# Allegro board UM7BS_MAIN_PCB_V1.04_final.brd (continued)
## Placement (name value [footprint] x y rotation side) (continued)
R339  39.2K  [RC0402N]  27.6 26.23 90 bottom
R340  20K  [RC0402N]  26.76 26.23 90 bottom
R341  1K  [RC0402N]  32.66 26.65 180 bottom
R342  10k  [RC0402N]  32.66 27.45 0 bottom
R343  0  [RC0603N]  31.47 32.55 0 bottom
R344  0  [RC0603N]  31.45 31.31 0 bottom
R345  0  [RC0402N]  115.86 93.86 270 bottom
R346  1K  [RC0402N]  31.14 41.12 270 bottom
R347  0  [RC0603N]  34.77 19.95 180 bottom
R348  0  [RC0603N]  26.98 19.88 180 bottom
R349  10k  [RC0402N]  25.37 25.38 180 bottom
R350  10K  [RC0402N]  37.57 37.65 0 bottom
R351  10K  [RC0402N]  39.17 35.26 90 bottom
R352  0  [RC0603N]  21.96 28.35 180 top
R353  100k  [RC0402N]  39.15 31.9 270 bottom
R354  0  [RC0603N]  25.7 29.79 90 top
R355  10k  [RC0402N]  34.98 22.78 180 bottom
R356  1k  [RC0402N]  22.4 29.38 0 top
R357  1k  [RC0402N]  23.86 29.17 270 top
R358  0  [RC0402N]  39.18 37.06 270 bottom
R359  1k  [RC0402N]  40.44 36.21 90 bottom
R360  0  [RC0603N]  9.17 18.35 0 top
R361  0  [RC0603N]  9.16 19.6 0 top
R362  0  [RC0603N]  242.16 10.4 270 top
R363  0  [RC0603N]  240.94 10.4 270 top
R364  10K  [RC0402N]  225.56 19.93 0 bottom
R365  100k  [RC0402N]  223.19 24.58 180 bottom
R366  27K  [RC0402N]  114.86 100.86 90 top
R367  0  [RC0402N]  105.56 94.62 90 bottom
R372  0  [RC0402N]  228.04 16.08 180 bottom
R374  0  [RC0603N]  218.19 15.61 180 bottom
R375  0  [RC0402N]  214.83 13.68 180 bottom
R380  10k  [RC0402N]  217.72 12.25 0 bottom
R385  0  [RC0402N]  64.41 72.7 180 bottom
R386  10k  [RC0402N]  75.38 72.42 0 bottom
R387  0  [RC0402N]  64.41 71.81 180 bottom
R388  0  [RC0603N]  82.34 78.94 0 bottom
R389  0  [RC0805N]  82.34 77 180 bottom
R390  0  [RC0402N]  78.16 70.7 180 bottom
R391  10k  [RC0402N]  77.97 69.53 180 bottom
R392  10k  [RC0402N]  43.84 69.94 0 bottom
R393  0  [RC0402N]  64.41 64.19 180 bottom
R394  10k  [RC0402N]  43.84 70.73 0 bottom
R395  0  [RC0402N]  43.83 65.14 180 bottom
R396  10k  [RC0402N]  54.89 74.6 270 bottom
R397  0  [RC0402N]  43.83 65.97 180 bottom
R398  0  [RC0402N]  46.51 74.6 90 bottom
R399  10k  [RC0402N]  55.9 74.6 270 bottom
R400  0  [RC0402N]  49.94 76.89 90 bottom
R401  10k  [RC0402N]  51.84 74.6 270 bottom
R402  10k  [RC0402N]  52.86 74.6 270 bottom
R403  0  [RC0402N]  49.94 74.6 90 bottom
R404  0  [RC0402N]  45.69 74.6 90 bottom
R405  10k  [RC0402N]  56.92 74.6 270 bottom
R406  100k  [RC0402N]  72.29 70.41 90 bottom
R407  0  [RC0402N]  77.46 62.71 0 top
R408  10k  [RC0402N]  57.94 74.6 270 bottom
R409  0  [RC0603N]  64.79 69.65 0 bottom
R410  0  [RC0603N]  64.79 68.25 0 bottom
R411  0  [RC0402N]  43.84 69.05 180 bottom
R412  0  [RC0402N]  77.46 68.77 180 top
R413  100k  [RC0402N]  72.29 68 270 bottom
R414  10k  [RC0402N]  74.79 68.13 180 bottom
R415  0  [RC0402N]  77.46 67.88 180 top
R416  10k  [RC0402N]  74.79 66.86 180 bottom
R417  0  [RC0402N]  77.46 66.74 180 top
R418  10k  [RC0402N]  43.84 66.85 0 bottom
R419  10k  [RC0402N]  43.84 67.74 0 bottom
R422  0  [RC0402N]  64.41 66.09 180 bottom
R423  0  [RC0402N]  54.86 77 270 bottom
R424  0  [RC0402N]  55.84 77 270 bottom
R427  10k  [RC0402N]  77.97 65.47 180 bottom
R428  100  [RC0402N]  64.4 61.99 0 bottom
R429  0  [RC0402N]  72.29 65.58 90 bottom
R430  0  [RC0402N]  65.85 58.86 90 bottom
R431  0  [RC0402N]  64.41 70.79 180 bottom
R432  0  [RC0402N]  77.46 64.32 180 top
R433  0  [RC0402N]  77.47 63.52 180 top
R434  10k  [RC0402N]  74.79 63.05 180 bottom
R435  0  [RC0402N]  55.14 53.91 90 bottom
R438  0  [RC0402N]  64.41 65.08 180 bottom
R439  0  [RC0402N]  54.37 53.91 270 bottom
R440  0  [RC0402N]  77.45 61.42 180 top
R441  10k  [RC0402N]  76.71 61.56 270 bottom
R442  0  [RC0402N]  58.95 74.6 270 bottom
R443  10k  [RC0402N]  53.6 53.91 90 bottom
R444  0  [RC0402N]  59.97 76.89 90 bottom
R445  100k  [RC0402N]  62.14 63.07 0 top
R446  0  [RC0402N]  59.97 74.6 90 bottom
R447  4.7K  [RC0402N]  67.87 60.9 180 bottom
R448  5.6K  [RC0402N]  67.87 60.11 180 bottom
R449  0  [RC0402N]  49.05 74.6 270 bottom
R450  0  [RC0402N]  50.94 75.02 90 bottom
R452  0  [RC0402N]  48.16 74.6 90 bottom
R453  10k  [RC0402N]  44.25 58.6 90 bottom
R454  0  [RC0402N]  43.73 59.93 0 bottom
R455  0  [RC0402N]  43.84 63.57 0 bottom
R456  10k  [RC0402N]  50.13 60.85 90 top
R457  0  [RC0402N]  44.36 80.19 90 top
R458  0  [RC0402N]  61.75 76 0 bottom
R459  10M  [RC0402N]  63.14 74.85 90 bottom
R460  4.7K  [RC0402N]  47.49 81.68 180 top
R461  4.7K  [RC0402N]  45.48 74.8 90 top
R462  0  [RC0402N]  53.87 74.6 90 bottom
R463  0  [RC0402N]  58.95 76.89 90 bottom
R464  100k  [RC0402N]  51.02 60.85 90 top
R465  0  [RC0603N]  113.36 83.11 180 top
R466  0  [RC0603N]  113.36 85.13 180 top
R467  0  [RC0402N]  44.2 56.3 90 bottom
R469  0  [RC0603N]  9.59 89.65 90 top
R470  0  [RC0603N]  8.38 89.65 90 top
R471  0  [RC0603N]  5.27 89.92 90 top
R472  1.8k  [RC0603N]  18.22 85.73 90 bottom
R473  0  [RC0603N]  6.47 89.92 90 top
R474  1k  [RC0603N]  19.47 85.73 270 bottom
R475  1k  [RC0402N]  16.33 81.88 0 bottom
R476  0  [RC0603N]  11.33 89.4 90 top
R477  0  [RC0603N]  12.54 89.4 90 top
R479  1.8k  [RC0603N]  46.17 91.2 270 bottom
R481  1k  [RC0603N]  48.73 92.7 270 bottom
R482  1k  [RC0402N]  51.51 90.03 90 bottom
R483  0  [RC0603N]  46.96 21.16 0 top
R484  30k  [RC0603N]  42.82 24.8 0 top
R485  0  [RC0603N]  46.96 19.89 0 top
R486  1k  [RC0603N]  42.53 23.47 0 top
R487  1k  [RC0402N]  40.57 22.45 180 top
R488  0  [RC0603N]  62.54 21.2 0 top
R489  0  [RC0603N]  62.54 19.93 0 top
R490  30k  [RC0603N]  59.04 17.44 0 top
R491  1k  [RC0603N]  59.04 18.67 180 top
R492  1k  [RC0402N]  59.74 11.85 180 top
R493  2.2  [RC0805N]  115.73 27.42 0 top
R494  2K  [RC1206N]  140.49 20.92 90 bottom
R495  51m  [RC0805N]  110.5 93.32 0 top
R496  390K  [RC0603N]  140.86 24.77 270 bottom
R497  100  [RC1206N]  137.06 27.56 0 bottom
R498  100k  [RC0402N]  138.04 25.5 0 bottom
R499  1M  [RC0402N]  139.03 21.45 90 bottom
R500  0  [RC0402N]  132.56 21.43 180 bottom
R501  100k  [RC0402N]  130.01 25.4 270 bottom
R509  100  [RC0402N]  100.79 11.32 0 top
R528  0  [RC0402N]  117.57 91.03 180 bottom
R530  0  [RC0402N]  117.57 89.43 0 bottom
R531  1M  [RC0402N]  119.37 89.43 0 bottom
R534  0  [RC0402N]  117.57 90.21 180 bottom
R536  10K  [RC0402N]  104.71 92.17 90 bottom
R537  100k  [RC0402N]  101.77 90.9 180 bottom
R538  1M  [RC0402N]  96.49 90.98 180 bottom
R539  10K  [RC0402N]  146.86 88.35 270 bottom
R540  100k  [RC0402N]  148.69 85.3 0 bottom
R541  0  [RC0402N]  144.47 84.03 90 bottom
R542  0  [RC0402N]  146.86 86.54 270 bottom
R543  0  [RC0402N]  143.68 84.03 90 bottom
R544  1M  [RC0402N]  148.62 80.08 180 bottom
R551  1K  [RC0402N]  36.39 74.55 270 bottom
R552  0  [RC0402N]  50.01 54.11 270 bottom
R553  12k  [RC0402N]  152.63 17.84 90 top
R554  0  [RC0402N]  167.78 37.13 90 bottom
R555  20K  [RC0402N]  141.25 42.01 0 bottom
R556  30k  [RC0603N]  143.49 42.01 0 bottom
R557  100k  [RC0402N]  142.04 45.52 90 bottom
R558  10k  [RC0402N]  154.95 16.47 270 top
R559  0  [RC0402N]  164.99 31.21 180 bottom
R560  0  [RC0402N]  77.07 43.92 0 bottom
R561  0  [RC0402N]  81.53 36.42 180 bottom
R562  0  [RC0402N]  64.41 63.38 0 bottom
R563  0  [RC0402N]  196.11 40.07 90 bottom
R564  0  [RC0402N]  89.58 36.15 0 top
R565  0  [RC0402N]  194.09 48.09 180 bottom
R567  0  [RC0402N]  180.31 74.68 180 bottom
R568  3.3K  [RC0402N]  154.29 42.11 180 top
R569  0  [RC0402N]  180.75 50.57 90 bottom
R570  0  [RC0402N]  188.7 43.1 270 bottom
R571  0  [RC0402N]  187.69 43.09 270 bottom
R572  1k  [RC0402N]  187.69 45.9 270 bottom
R573  1k  [RC0402N]  188.7 45.9 270 bottom
R574  0  [RC0603N]  183.54 28.61 0 top
R575  0  [RC0402N]  185.82 30.03 270 top
R576  10k  [RC0402N]  187.43 35.49 90 bottom
R577  0  [RC0603N]  168.82 87.36 180 top
R578  0  [RC0603N]  168.82 88.63 180 top
R579  2.2  [RC0603N]  180.4 24.37 270 top
R580  2.2  [RC0603N]  155.35 36.42 270 top
R581  2.2  [RC0603N]  198.77 21.88 90 top
R582  0  [RC0603N]  166.76 28.12 270 bottom
R583  0  [RC0603N]  154.81 16.09 0 bottom
R584  10k  [RC0402N]  128.33 11.87 0 top
R585  1k  [RC0402N]  198.37 98.1 180 top
R586  10K_NTC_3300  [RC0402N]  198.37 99.24 180 top
R587  100k  [RC0402N]  164.61 15.28 180 bottom
R588  0  [RC0402N]  195.46 31.87 270 bottom
R589  0  [RC0402N]  162.17 15.8 180 bottom
R590  10k  [RC0402N]  209.07 40.06 0 top
R591  10k  [RC0402N]  67.86 61.78 180 bottom
R592  10k  [RC0402N]  158.6 58.35 270 bottom
R593  182  [RC0402N]  198.75 48.05 270 bottom
R594  0  [RC0402N]  172.11 75.46 0 bottom
R595  0  [RC0402N]  197.68 80.15 90 top
R596  0  [RC0402N]  196.65 80.15 270 top
R597  0  [RC0402N]  183.09 35.49 270 bottom
R598  0  [RC0402N]  182.6 37.65 270 bottom
R599  0  [RC0402N]  174.14 35.48 90 bottom
R600  1k  [RC0402N]  117.05 59.98 270 bottom
R601  1k  [RC0402N]  116.06 59.98 270 bottom
R602  0  [RC0402N]  167.02 51.42 180 bottom
R603  0  [RC0402N]  79.62 57.51 180 bottom
R604  0  [RC0402N]  79.62 58.3 180 bottom
R605  0  [RC0402N]  78.64 56.69 180 bottom
R606  0  [RC0402N]  116.74 84.48 180 bottom
R616  100k  [RC0402N]  116.39 86.85 180 bottom
R636  18.7K  [RC0603N]  119.2 83.11 180 top
R638  12K  [RC0603N]  127.41 83.26 180 bottom
R645  430k  [RC0603N]  114.86 98.1 90 top
R648  430k  [RC0603N]  127.41 82 0 bottom
R663  51m  [RC0805N]  110.5 91.49 0 top
R670  0  [RC0603N]  166.51 28.56 90 top
R681  20K  [RC0402N]  118.8 81.1 180 top
R707  51m  [RC0805N]  110.5 89.71 0 top
R746  10.5K  [RC0402N]  165.71 72.92 90 bottom
R748  1  [RC0603N]  100.36 55.95 90 bottom
R754  16k  [RC0603N]  127.41 84.53 0 bottom
R755  10.9k  [RC0603N]  119.21 86.61 0 top
R756  10k  [RC0603N]  119.21 85.12 180 top
R770  0  [RC0402N]  194.08 45.92 270 bottom
R784  0  [RC0402N]  228.11 14.4 180 bottom
R785  0  [RC0402N]  228.11 13.59 180 bottom
R786  0  [RC0402N]  237.79 14.63 270 bottom
R787  0  [RC0402N]  235.6 14.15 0 bottom
R788  0  [RC0402N]  232.87 16.51 0 bottom
R789  10K  [RC0402N]  232.99 14.72 180 bottom
R790  0  [RC0402N]  232.99 15.53 0 bottom
R800  10k  [RC0402N]  72.32 98.75 90 bottom
R801  1k  [RC0402N]  73.64 99.89 0 bottom
R802  100k  [RC0402N]  73.64 99.07 0 bottom
R821  10  [RC0402N]  167.1 39.45 90 bottom
R823  100  [RC0402N]  195.34 40.07 90 bottom
R825  100  [RC0402N]  155.69 30.29 90 top
R826  0  [RC0402N]  156.36 28.48 90 top
R827  100  [RC0402N]  156.47 30.29 270 top
R828  10k  [RC0402N]  47.32 74.6 90 bottom
R837  0  [RC0402N]  175.63 24.39 0 top
R838  0  [RC0402N]  197.32 20.66 270 bottom
R839  0  [RC0402N]  150.14 28.8 270 top
R840  2.2  [RC0603N]  162.07 10.9 0 top
R841  2.2  [RC0603N]  157.53 11.01 180 top
R842  100k  [RC0402N]  147.36 15.42 270 bottom
R843  0  [RC0402N]  147.66 16.71 0 bottom
R844  0  [RC0402N]  149.55 14.91 0 bottom
R848  0  [RC0402N]  194.85 45.92 270 bottom
R883  39K  [RC0603N]  114.86 100.86 270 top
R958  100k  [RC0402N]  124.42 82.57 0 bottom
R2978  0  [RC0603N]  40.82 89.2 180 top
R2979  0  [RC0603N]  40.82 90.43 180 top
R2980  0  [RC0603N]  35.21 89.91 90 top
R2981  0  [RC0603N]  36.51 89.91 90 top
R2982  0  [RC0603N]  33.53 89.65 90 top
R2983  0  [RC0603N]  32.24 89.65 90 top
R2984  10k  [RC0402N]  182.01 76.93 90 bottom
R3089  0  [RC0402N]  126.81 86.96 0 bottom
R3090  0  [RC0402N]  127.69 86.16 180 bottom
R3091  0  [RC0402N]  116.75 83.6 0 bottom
R3093  100  [RC0402N]  116.39 87.65 180 bottom
R3094  0  [RC0402N]  118.42 82.69 0 bottom
R3095  0  [RC0402N]  105.09 95.94 180 bottom
R3096  1M  [RC0402N]  114.86 98.1 90 top
R3097  0  [RC0402N]  104.62 94.62 90 bottom
R3098  0  [RC0603N]  113.36 81.11 180 top
R3099  0  [RC0603N]  113.36 87.12 180 top
R3100  51m  [RC0805N]  110.5 95.14 0 top
R3101  0  [RC0402N]  103.73 97.39 270 bottom
R3102  0  [RC0402N]  102.88 97.39 270 bottom
R3103  0  [RC0402N]  105.47 97.39 270 bottom
R3104  0  [RC0402N]  104.61 97.39 270 bottom
R3105  100K  [RC0402N]  155.57 50.38 180 bottom
R3106  24k  [RC0402N]  155.57 51.35 0 bottom
R3107  12k  [RC0402N]  155.57 52.18 180 bottom
R3108  100K  [RC0402N]  150.91 50.63 180 bottom
R3109  100K  [RC0402N]  167.86 72.93 270 bottom
R3112  0  [RC0402N]  167.64 69.17 0 bottom
R3113  24K  [RC0402N]  166.51 72.92 270 bottom
SW1  THBM02  [TH-SW-420P-2N]  122.33 8.39 0 top
SW2  SKRMABE010  [SW_330X390P_4N]  59.72 60.17 0 top
TP5  TP  [TEST120]  169.33 55.13 270 top
TP6  TP  [TEST120]  174.64 58.69 90 bottom
TP7  TP  [TEST120]  172.36 60.01 90 bottom
TP10  TP  [TEST120]  185.6 43.03 90 top
TP11  TP  [TEST120]  182.64 54.27 270 bottom
TP12  TP  [TEST120]  81.8 58.79 180 bottom
TP13  TP  [TEST120]  80.8 56.19 180 bottom
TP14  TP  [TEST120]  85.66 60.88 180 bottom
TP15  TP  [TEST120]  81.86 60.43 270 bottom
U1  BSW_MCP_EDS  [BGA78P66X53-1170N]  183.67 62.61 270 top
U2  EN25S64-104RIP  [VSOP127P790-8N]  158.48 44.53 90 top
U3  TPS22965  [SON50P200X200-8N]  152.38 45.16 270 top
U4  KH25U6439FZNI-10G  [SON127P500X600-8AN]  158.48 44.4 90 top
U5  TXS0102DQER  [SON35P100-8N]  114.07 45.47 270 bottom
U6  TXB0104RUTR  [UQFN40P200X170-12N]  77.46 58.23 180 bottom
U7  SN74AHC1G32  [SOT65P210-5N]  180.6 98.02 180 bottom
U8  KLMCG8GE2A  [BGA50P14X28-169AN]  181.97 27.87 270 bottom
U9  GL850G-SSOP28  [SSOP65P780-28N]  175.17 90.4 180 top
U10  TPS51275/C  [QFN40P300X300-20N]  121.2 61.76 90 bottom
U11  TPS650840  [QFN40P800X800-64N]  161.04 22.19 0 top
U15  APL3512A/B  [SOT95P280-5N]  134.94 86.15 0 bottom
U16  PS8625QFN56G  [QFN40P700X700-56AN]  152.51 96.17 180 bottom
U17  AT24C02A  [SOIC127P600-8N]  139.27 100.47 270 top
U18  AT24C02A  [SOIC127P600-8N]  153.66 83.03 180 bottom
U21  APL3512A/B  [SOT95P280-5N]  112.59 29.1 180 bottom
U22  RTL8105E/8111E  [QFN40P600X600-48N]  120.93 38.6 0 bottom
U23  HS00-04078  [SMD-TRANSF-127P-16N]  101.86 35.88 180 top
U24  HS00-04078  [SMD-TRANSF-127P-16N]  101.88 37.15 180 bottom
U25  ALC282  [QFN40P600X600-48AN]  24.83 34.84 180 bottom
U26  5_SN74LVC1G08DCKR  [SOT65P190-5N]  36.69 35.75 180 bottom
U27  SN74LVC1G08DCKR  [SOT65P190-5N]  227.91 18.36 270 bottom
U28  APL3512A/B  [SOT95P280-5N]  218.26 14.31 180 bottom
U29  TXB0101DCKR  [SOT65P210-6N]  78.44 72.46 180 bottom
U30  TXB0104RUTR  [UQFN40P200X170-12N]  77.46 67.63 180 bottom
U31  IT8528E/VG  [LQFP40P1600X1600-128N]  54.13 64.06 180 bottom
U32  TXB0104RUTR  [UQFN40P200X170-12N]  77.46 63.56 180 bottom
U33  SN74LVC1G06DCK  [SOT65P210-5N]  50.39 63.65 90 top
U34  EN25F16-100HIP  [SOIC127P800-8N]  48.92 76.11 90 top
U35  TPS2065  [SOT95P280-5N]  15.85 84.65 270 bottom
U36  TPD2EUSB30DRTR  [SOP35P100-3N]  5.9 91.97 0 top
U37  TPD2EUSB30DRTR  [SOP35P100-3N]  11.97 91.45 0 top
U38  TPS2065  [SOT95P280-5N]  48.96 89.56 0 bottom
U39  TPS2065  [SOT95P280-5N]  41.8 20.36 180 top
U40  TPS2065  [SOT95P280-5N]  60.23 14.68 270 top
U41  APW7228BRI-TRG  [TSSOP65P640-16AN]  121.89 85.88 180 bottom
U42  SN74LVC1G08DCKR  [SOT65P190-5N]  144.64 86.36 180 bottom
U44  APL3512A/B  [SOT95P280-5N]  167.32 34.14 90 bottom
U46  APL5701ABI  [SOT95P280-5N]  144.35 44.76 270 bottom
U53  APL5932C/D  [TDFN50P300X300-10N]  152.71 52.76 180 bottom
U95  GL834L  [QFN50P400X400-24BN]  74.02 94.62 180 bottom
U2523  TPD2EUSB30DRTR  [SOP35P100-3N]  32.82 91.73 0 top
U2524  TPD2EUSB30DRTR  [SOP35P100-3N]  38.71 89.83 90 top
U2525  APL5932C/D  [TDFN50P300X300-10N]  165.04 70.11 270 bottom
X1  OSC-4_7  [OSC170P320X250-4N]  165.6 66.09 180 top
X2  32.768KHz  [OSC120P150X670-4L]  161.71 49.94 180 bottom
X3  Q13MC1461000200SM26BSPRC  [OSC127P200X600-2L]  161.71 49.06 180 bottom
X4  12MHz  [OSC170P320X250-4N]  183.82 89.7 90 top
X5  X3S025000FK1H  [OSC170P320X250-4N]  121.44 29.84 180 bottom
X6  32.768KHz  [OSC120P150X670-4L]  69.37 74.98 270 bottom
X7  Q13MC1461000200SM26BSPRC  [OSC127P200X600-2L]  70.26 74.98 270 bottom

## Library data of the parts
B1 = MIC-2_0
C1 C2 C14-C21 C23 C24 C28 C33-C35 C38-C40 C42-C48 C52 C53 C56-C72 C78 C79 C81-C86 C88-C90 C95-C99 C108-C127 C129-C137 C139 C145-C155 C166 C167 C174 C187 C202 C203 C206 C207 C210 C211 C213 C214 C223-C247 C249-C261 C266 C268 C283 C284 C286 C288 C295 C301 C304-C311 C313-C316 C319 C320 C323-C332 C334 C336 C338-C345 C348-C353 C356 C358 C359 C362 C364-C373 C375-C402 C405 C409 C412-C429 C432 C435-C441 C444-C458 C488 C527 C557 C560-C562 C565 C566 C691 C700-C702 C704-C708 C710 C799-C801 C822 C823 C826-C831 C942 C2833-C2837 = C
C3-C13 C100-C107 C138 C140-C144 C281 C287 C290 C292 C299 C303 C346 C347 C442 C443 C2762 C2763 = C: signal model: C_CC0402N_100NF_100NF
C22 C25-C27 C165 C171 C263 C296 C312 C433 C434 = C: signal model: C_CC0402N_0.01UF_0.01uF
C29-C32 C36 C37 C41 C49-C51 C54 C55 C73-C77 C80 C87 C91-C94 C204 C205 C703 = C: alternate symbols: (T:CC0805N;B:CC0805M)
C128 C158 C160 C161 C164 C168 C173 C183-C186 C188-C190 C193-C195 C197-C201 C212 C215-C222 C264 C265 C267 C300 C333 C355 C357 C360 C361 C363 C374 C410 C411 C459-C462 C464-C466 C468 C607 C727 C992 C2838 = C: alternate symbols: (T:CC0603N;B:CC0603M)
C156 C159 C163 = C: alternate symbols: (T:CC0603N;B:CC0603M); signal model: C_CC0402N_0.01UF_0.01uF
C157 = C: alternate symbols: (T:CC0603N;B:CC0603M); signal model: C_CC0402N_100NF_100NF
C175 C176 C182 = C: alternate symbols: (T:CC0603N;B:CC0603M); signal model: C_CC0402N_0.1U_0.1u
C177-C181 C208 C209 = C: signal model: C_CC0402N_0.1U_0.1u
C297 C335 C337 C354 = C: alternate symbols: (T:CC1206N;B:CC1206M)
C298 C302 C603 = C: alternate symbols: (T:CC1210N;B:CC1210M)
CN1 = CN-DDR3-204
CN3 = CN-SATA-7+15+2-S
CN6 = RJ45_8+2
CN7 CN10 CN12 = CN2+2-S
CN9 = CN75+2-J8
CN11 = CN20+2-S
CN18 J4 = CN-USB-9+4
CN19 CN20 = CN-USB-4+2
CN21 = CN-JACK-3
CN22 = CN2-S
CN23 = SD_11+4
CN24 = BAT_CON_2
CN25 = CN4+2-S
CN26 = CN75+2-S1_1
CN35 = CN40d+2_1
CN40 = CN8d_1
CP1 CP3 CP5 CP8-CP13 CP15-CP21 = C_P: alternate symbols: (T:CCP7343N;B:CCP7343M)
CP4 CP6 CP7 CP14 CP50 = C_P
D1-D3 D12-D14 D17-D21 D26 D27 D30 D38 D42-D44 D2512 D2513 = D
D4 D5 = D_2PN: alternate symbols: (T:SOT95P280-3N;B:SOT95P280-3M)
D8-D11 D22 D23 D28 D29 D31 = D: alternate symbols: (T:sod2514n;B:SOD2514M)
F2-F6 F8 F9 = FUSE
FB1 FB2 FB8-FB14 FB16 FB17 FB19 FB20 FB25 FB27 = FB
FB4-FB7 FB15 FB24 FB37 FB38 = FB: alternate symbols: (T:FB0603N;B:FB0603M)
FIL1-FIL7 FIL9-FIL11 FIL14-FIL16 = FIL4_DXW21BN7511TB
J2 J3 = CN-EARPHONE-5_15
J5 = CN6+2-S
L1-L10 L32 = L
LED1 LED2 = LED
MARK1-MARK8 = MARK
MH1-MH13 = H
Q1 Q16 = NPN-BEC+2R: alternate symbols: (T:SOT65P210-3N;B:SOT65P210-3M)
Q4-Q8 Q31 Q35 Q38 Q40 Q41 Q49 Q51-Q53 = NMOS-GSD
Q9 Q14 Q15 = 7_SM7302ESKP
Q10 Q13 = SI4814: alternate symbols: (T:SOIC127P600-8N;B:SOIC127P600-8M)
Q18 Q21 = PWR_N_MOSFET: alternate symbols: (T:SOIC127P600-8N;B:SOIC127P600-8M)
Q19 Q20 Q22 Q23 Q36 Q42 Q43 Q45 Q46 = NMOS-GSD: alternate symbols: (T:SOT95P240-3N;B:SOT95P240-3M)
Q30 Q37 Q39 Q48 Q50 = NMOS-GSD_0
Q44 = PWR_P_MOSFET: alternate symbols: (T:SOIC127P600-8N;B:SOIC127P600-8M)
Q95 = 3_APM1110NU
R1-R3 R14-R22 R24-R30 R34 R35 R43-R46 R51-R69 R71 R72 R76-R86 R88-R95 R97 R100 R103 R105 R108 R109 R111 R113 R115 R119 R121-R127 R129-R153 R155 R163 R166 R169-R179 R181-R183 R185-R188 R193 R195 R196 R200 R203 R209 R210 R213 R225 R227-R234 R249 R253 R255 R258 R262 R263 R266 R267 R269-R277 R296 R297 R300 R301 R304-R306 R308 R310 R311 R313 R321-R325 R327-R329 R331-R339 R342 R345 R347-R349 R352 R354-R357 R359-R363 R365-R367 R372 R375 R380 R385-R387 R390-R396 R398-R408 R411-R419 R422 R427-R435 R438-R450 R452-R459 R462-R464 R467 R472 R475 R479 R482 R487 R492 R497-R501 R509 R530 R531 R538 R541-R544 R552-R555 R557-R559 R562 R563 R565 R567 R569-R576 R579-R586 R588-R606 R645 R648 R670 R681 R746 R754-R756 R770 R784-R788 R790 R800-R802 R821 R823 R825-R828 R837-R841 R843 R844 R848 R883 R2984 R3089-R3091 R3093-R3095 R3097-R3099 R3101-R3104 R3107 R3112 R3113 = R
R9 R40-R42 R118 R180 R184 R189 R190 R194 R197-R199 R205 R214-R216 R220 R221 R246 R291 R294 R302 R303 R307 R309 R317 R341 R343 R344 R346 R353 R388 R409 R410 R460 R461 R474 R481 R484 R486 R490 R491 R495 R496 R537 R540 R551 R556 R568 R587 R616 R636 R663 R707 R748 R842 R958 R3096 R3100 = R: alternate symbols: (T:RC0603N;B:RC0603M)
R31-R33 R36-R39 R87 R101 R156-R162 R164 R165 R167 R168 R211 R298 = R: signal model: R_RC0402N_0_0
R47-R50 = R: signal model: R_RC0402N_33_33
R70 R73-R75 = R: signal model: R_RC0402N_22_22
R154 R206-R208 = R: signal model: R_0_RC0402N_0_0
R191 R192 R493 = R_0: alternate symbols: (T:RC0603N;B:RC0603M)
R201 R202 R204 = R: alternate symbols: (T:RC0603N;B:RC0603M); signal model: R_0_RC0402N_0_0
R217-R219 R222-R224 R251 R259 R260 R268 R330 R340 R350 R351 R358 R397 R423 R424 R528 R534 R536 R539 R560 R561 R564 R638 R789 R3105 R3106 R3108 R3109 = R_0
R247 R295 R374 R389 = R: alternate symbols: (T:RC0805N;B:RC0805M)
R299 = R: alternate symbols: (T:RC0603N;B:RC0603M); signal model: R_RC0402N_0_0
R312 R314-R316 R318-R320 R326 = R: alternate symbols: (T:RC0603N;B:RC0603M); signal model: C_CC0402N_100NF_100NF
R364 = R_0: signal model: R_RC0402N_0_0
R465 R466 = R: signal model: C_CC0402N_100NF_100NF
R469-R471 R473 R476 R477 R483 R485 R488 R489 R577 R578 R2978-R2983 = R: signal model: R_RC0603N_0_0
R494 = R: alternate symbols: (T:RC1206N;B:RC1206M)
SW1 = SW-2+2
SW2 = SW-4_2
TP5-TP7 TP10-TP15 = TP
U1 = 1170_BSW_MCP_EDS
U2 = 8_EN25S64
U3 = 8+1_TPS22965
U4 = 8+1_KH25U6439F_1
U5 = 8_TXS0102DQER
U6 U30 U32 = 12_TXB0104RUTR
U7 = 5_SN74AHC1G09DCK
U8 = 169_KLMCG8GE2A
U9 = 28_GL850GSSOP28
U10 = 20+1_TPS51275/C
U11 = 64+1_TPS650840
U15 U21 U28 U44 = 5_APL3512
U16 = 56+1_PS8625QFN56G
U17 U18 = 8_AT24C02A
U22 = 48+1_RTL8105E/8111E
U23 U24 = H0056
U25 = 48+1_ALC282
U26 U27 U42 = 5_SN74LVC1G08DCKR
U29 = 6_TXB0101DCKR
U31 = 128_IT8528E/VG
U33 = 5_SN74LVC1G06DCK
U34 = 8_MX25L4005AMC-12G
U35 U38-U40 = 5_APL3511
U36 U37 U2523 U2524 = 3_TPD2EUSB30DRTR
U41 = 16+1_APW7228BRI
U46 = 5_APL5325
U53 U2525 = 10+1_APL5932C/D
U95 = 24+1_GL834L
X1 X4 X5 = OSC-4_7
X2 X6 = OSC-4_4
X3 X7 = OSC-2

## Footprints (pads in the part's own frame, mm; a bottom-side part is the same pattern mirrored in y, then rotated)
BGA50P14X28-169AN
  round 0.254 smd: A4(-1.751,6.752) A6(-0.75,6.752) A9(0.75,6.752) A11(1.75,6.752) AA1(-3.251,-3.251) AA2(-2.751,-3.251) AA3(-2.251,-3.251) AA4(-1.751,-3.251) AA5(-1.25,-3.251) AA6(-0.75,-3.251) AA7(-0.25,-3.251) AA8(0.25,-3.251) AA9(0.75,-3.251) AA10(1.25,-3.251) AA11(1.75,-3.251) AA12(2.25,-3.251) AA13(2.751,-3.251) AA14(3.251,-3.251) AE1(-3.251,-5.251) AE14(3.251,-5.251) AG2(-2.751,-6.251) AG13(2.751,-6.251) AH4(-1.751,-6.752) AH6(-0.75,-6.752) AH9(0.75,-6.752) AH11(1.75,-6.752) B2(-2.751,6.251) B13(2.751,6.251) D1(-3.251,5.251) D14(3.251,5.251) H1(-3.251,3.251) H2(-2.751,3.251) H3(-2.251,3.251) H4(-1.751,3.251) H5(-1.25,3.251) H6(-0.75,3.251) H7(-0.25,3.251) H8(0.25,3.251) H9(0.75,3.251) H10(1.25,3.251) H11(1.75,3.251) H12(2.25,3.251) H13(2.751,3.251) H14(3.251,3.251) J1(-3.251,2.751) J2(-2.751,2.751) J3(-2.251,2.751) J4(-1.751,2.751) J5(-1.25,2.751) J6(-0.75,2.751) J7(-0.25,2.751) J8(0.25,2.751) J9(0.75,2.751) J10(1.25,2.751) J11(1.75,2.751) J12(2.25,2.751) J13(2.751,2.751) J14(3.251,2.751) K1(-3.251,2.251) K2(-2.751,2.251) K3(-2.251,2.251) K4(-1.751,2.251) K5(-1.25,2.251) K6(-0.75,2.251) K7(-0.25,2.251) K8(0.25,2.251) K9(0.75,2.251) K10(1.25,2.251) K11(1.75,2.251) K12(2.25,2.251) K13(2.751,2.251) K14(3.251,2.251) L1(-3.251,1.751) L2(-2.751,1.751) L3(-2.251,1.751) L4(-1.751,1.751) L12(2.25,1.751) L13(2.751,1.751) L14(3.251,1.751) M1(-3.251,1.25) M2(-2.751,1.25) M3(-2.251,1.25) M5(-1.25,1.25) M6(-0.75,1.25) M7(-0.25,1.25) M8(0.25,1.25) M9(0.75,1.25) M10(1.25,1.25) M12(2.25,1.25) M13(2.751,1.25) M14(3.251,1.25) N1(-3.251,0.75) N2(-2.751,0.75) N3(-2.251,0.75) N5(-1.25,0.75) N10(1.25,0.75) N12(2.25,0.75) N13(2.751,0.75) N14(3.251,0.75) P1(-3.251,0.25) P2(-2.751,0.25) P3(-2.251,0.25) P5(-1.25,0.25) P10(1.25,0.25) P12(2.25,0.25) P13(2.751,0.25) P14(3.251,0.25) R1(-3.251,-0.25) R2(-2.751,-0.25) R3(-2.251,-0.25) R5(-1.25,-0.25) R10(1.25,-0.25) R12(2.25,-0.25) R13(2.751,-0.25) R14(3.251,-0.25) T1(-3.251,-0.75) T2(-2.751,-0.75) T3(-2.251,-0.75) T5(-1.25,-0.75) T10(1.25,-0.75) T12(2.25,-0.75) T13(2.751,-0.75) T14(3.251,-0.75) U1(-3.251,-1.25) U2(-2.751,-1.25) U3(-2.251,-1.25) U5(-1.25,-1.25) U6(-0.75,-1.25) U7(-0.25,-1.25) U8(0.25,-1.25) U9(0.75,-1.25) U10(1.25,-1.25) U12(2.25,-1.25) U13(2.751,-1.25) U14(3.251,-1.25) V1(-3.251,-1.75) V2(-2.751,-1.75) V3(-2.251,-1.75) V12(2.25,-1.75) V13(2.751,-1.75) V14(3.251,-1.75) W1(-3.251,-2.25) W2(-2.751,-2.25) W3(-2.251,-2.25) W4(-1.751,-2.25) W5(-1.25,-2.25) W6(-0.75,-2.25) W7(-0.25,-2.25) W8(0.25,-2.25) W9(0.75,-2.25) W10(1.25,-2.25) W11(1.75,-2.25) W12(2.25,-2.25) W13(2.751,-2.25) W14(3.251,-2.25) Y1(-3.251,-2.751) Y2(-2.751,-2.751) Y3(-2.251,-2.751) Y4(-1.751,-2.751) Y5(-1.25,-2.751) Y6(-0.75,-2.751) Y7(-0.25,-2.751) Y8(0.25,-2.751) Y9(0.75,-2.751) Y10(1.25,-2.751) Y11(1.75,-2.751) Y12(2.25,-2.751) Y13(2.751,-2.751) Y14(3.251,-2.751)
BGA78P66X53-1170N
  round 0.47 smd: A3(11.951,-11.814) A52(-12.383,-11.814) B2(12.383,-11.383) B53(-12.814,-11.383) BH1(12.814,11.383) BH53(-12.814,11.383) BJ2(12.383,11.814) BJ52(-12.383,11.814) C1(12.814,-10.951)
  round 0.356 smd: A5(11.17,-11.814) A6(10.447,-11.814) A7(9.748,-11.814) A9(8.836,-11.814) A47(-9.621,-11.814) A48(-10.294,-11.814) A49(-10.992,-11.814) A51(-11.773,-11.814) B4(11.632,-11.238) B5(11.038,-11.222) B6(10.445,-11.221) B8(9.258,-11.224) B46(-9.258,-11.224) B48(-10.445,-11.221) B49(-11.038,-11.222) B50(-11.632,-11.238) B52(-12.225,-11.225) BC1(12.814,8.621) BC2(12.246,8.852) BC52(-12.246,8.852) BC53(-12.814,8.621) BD1(12.814,9.294) BD2(12.221,9.445) BD52(-12.221,9.445) BD53(-12.814,9.294) BE1(12.814,9.992) BE2(12.222,10.038) BE52(-12.222,10.038) BE53(-12.814,9.992) BF2(12.238,10.632) BF52(-12.238,10.632) BG1(12.814,10.773) BG3(11.644,10.644) BG51(-11.644,10.644) BG53(-12.814,10.773) BH2(12.225,11.225) BH4(11.632,11.238) BH5(11.038,11.222) BH6(10.445,11.221) BH8(9.258,11.224) BH46(-9.258,11.224) BH48(-10.445,11.221) BH49(-11.038,11.222) BH50(-11.632,11.238) BH52(-12.225,11.225) BJ3(11.773,11.814) BJ5(10.992,11.814) BJ6(10.294,11.814) BJ7(9.621,11.814) BJ47(-9.621,11.814) BJ48(-10.294,11.814) BJ49(-10.992,11.814) BJ51(-11.773,11.814) C3(11.644,-10.644) C51(-11.644,-10.644) C53(-12.814,-10.773) D2(12.238,-10.632) D52(-12.238,-10.632) E1(12.814,-10.17) E2(12.222,-10.038) E52(-12.222,-10.038) E53(-12.814,-9.992) F1(12.814,-9.447) F2(12.221,-9.445) F52(-12.221,-9.445) F53(-12.814,-9.294) G1(12.814,-8.679) G2(12.246,-8.852) G52(-12.246,-8.852) G53(-12.814,-8.621) J1(12.814,-7.816)
  oval 0.254x0.343 smd: A11(7.774,-11.814) A13(6.803,-11.814) A15(5.831,-11.814) A17(4.859,-11.814) A19(3.887,-11.814) A21(2.915,-11.814) A23(1.944,-11.814) A25(0.972,-11.814) A27(0,-11.814) A29(-0.972,-11.814) A31(-1.944,-11.814) A33(-2.915,-11.814) A35(-3.887,-11.814) A37(-4.859,-11.814) A39(-5.831,-11.814) A41(-6.803,-11.814) A43(-7.774,-11.814) A45(-8.746,-11.814) BJ9(8.746,11.814) BJ11(7.774,11.814) BJ13(6.803,11.814) BJ15(5.831,11.814) BJ17(4.859,11.814) BJ19(3.887,11.814) BJ21(2.915,11.814) BJ23(1.944,11.814) BJ25(0.972,11.814) BJ27(0,11.814) BJ29(-0.972,11.814) BJ31(-1.944,11.814) BJ33(-2.915,11.814) BJ35(-3.887,11.814) BJ37(-4.859,11.814) BJ39(-5.831,11.814) BJ41(-6.803,11.814) BJ43(-7.774,11.814) BJ45(-8.746,11.814)
  oval 0.343x0.254 smd: AA1(12.814,-1.944) AA53(-12.814,-1.944) AC1(12.814,-0.972) AC53(-12.814,-0.972) AE1(12.814,0) AE53(-12.814,0) AG1(12.814,0.972) AG53(-12.814,0.972) AJ1(12.814,1.944) AJ53(-12.814,1.944) AL1(12.814,2.915) AL53(-12.814,2.915) AN1(12.814,3.887) AN53(-12.814,3.887) AR1(12.814,4.859) AR53(-12.814,4.859) AU1(12.814,5.831) AU53(-12.814,5.831) AW1(12.814,6.803) AW53(-12.814,6.803) BA1(12.814,7.774) BA53(-12.814,7.774) J53(-12.814,-7.774) L1(12.814,-6.803) L53(-12.814,-6.803) N1(12.814,-5.831) N53(-12.814,-5.831) R1(12.814,-4.859) R53(-12.814,-4.859) U1(12.814,-3.887) U53(-12.814,-3.887) W1(12.814,-2.915) W53(-12.814,-2.915)
  round 0.279 smd: AA3(12.071,-1.944) AA51(-12.071,-1.944) AB2(12.429,-1.458) AB3(11.73,-1.458) AB51(-11.73,-1.458) AB52(-12.429,-1.458) AC3(12.071,-0.972) AC51(-12.071,-0.972) AD2(12.429,-0.486) AD3(11.715,-0.48) AD51(-11.715,-0.48) AD52(-12.429,-0.486) AE3(12.071,0) AE4(11.366,0) AE50(-11.366,0) AE51(-12.071,0) AF2(12.429,0.486) AF3(11.715,0.48) AF51(-11.715,0.48) AF52(-12.429,0.486) AG3(12.071,0.972) AG51(-12.071,0.972) AH2(12.429,1.458) AH3(11.73,1.458) AH51(-11.73,1.458) AH52(-12.429,1.458) AJ3(12.071,1.944) AJ51(-12.071,1.944) AK2(12.429,2.43) AK3(11.73,2.43) AK51(-11.73,2.43) AK52(-12.429,2.43) AL3(12.071,2.915) AL51(-12.071,2.915) AM2(12.429,3.401) AM3(11.73,3.401) AM51(-11.73,3.401) AM52(-12.429,3.401) AN3(12.071,3.887) AN51(-12.071,3.887) AP2(12.429,4.373) AP3(11.73,4.373) AP51(-11.73,4.373) AP52(-12.429,4.373) AR3(12.071,4.859) AR51(-12.071,4.859) AT2(12.429,5.345) AT3(11.73,5.345) AT51(-11.73,5.345) AT52(-12.429,5.345) AU3(12.071,5.831) AU51(-12.071,5.831) AV2(12.429,6.317) AV3(11.73,6.317) AV51(-11.73,6.317) AV52(-12.429,6.317) AW3(12.071,6.803) AW51(-12.071,6.803) AY2(12.429,7.289) AY3(11.73,7.289) AY51(-11.73,7.289) AY52(-12.429,7.289) B10(8.26,-11.429) B12(7.289,-11.429) B14(6.317,-11.429) B16(5.345,-11.429) B18(4.373,-11.429) B20(3.401,-11.429) B22(2.43,-11.429) B24(1.458,-11.429) B26(0.486,-11.429) B28(-0.486,-11.429) B30(-1.458,-11.429) B32(-2.43,-11.429) B34(-3.401,-11.429) B36(-4.373,-11.429) B38(-5.345,-11.429) B40(-6.317,-11.429) B42(-7.289,-11.429) B44(-8.26,-11.429) BA3(12.071,7.774) BA51(-12.071,7.774) BB3(11.929,8.351) BB51(-11.929,8.351) BF27(0,10.366) BG9(8.698,11.028) BG11(7.774,11.071) BG12(7.289,10.73) BG13(6.803,11.071) BG14(6.317,10.73) BG15(5.831,11.071) BG16(5.345,10.73) BG17(4.859,11.071) BG18(4.373,10.73) BG19(3.887,11.071) BG20(3.401,10.73) BG21(2.915,11.071) BG22(2.43,10.73) BG23(1.944,11.071) BG24(1.458,10.73) BG25(0.972,11.071) BG26(0.48,10.715) BG27(0,11.071) BG28(-0.48,10.715) BG29(-0.972,11.071) BG30(-1.458,10.73) BG31(-1.944,11.071) BG32(-2.43,10.73) BG33(-2.915,11.071) BG34(-3.401,10.73) BG35(-3.887,11.071) BG36(-4.373,10.73) BG37(-4.859,11.071) BG38(-5.345,10.73) BG39(-5.831,11.071) BG40(-6.317,10.73) BG41(-6.803,11.071) BG42(-7.289,10.73) BG43(-7.774,11.071) BG45(-8.698,11.028) BH10(8.26,11.429) BH12(7.289,11.429) BH14(6.317,11.429) BH16(5.345,11.429) BH18(4.373,11.429) BH20(3.401,11.429) BH22(2.43,11.429) BH24(1.458,11.429) BH26(0.486,11.429) BH28(-0.486,11.429) BH30(-1.458,11.429) BH32(-2.43,11.429) BH34(-3.401,11.429) BH36(-4.373,11.429) BH38(-5.345,11.429) BH40(-6.317,11.429) BH42(-7.289,11.429) BH44(-8.26,11.429) C9(8.698,-11.028) C11(7.774,-11.071) C12(7.289,-10.73) C13(6.803,-11.071) C14(6.317,-10.73) C15(5.831,-11.071) C16(5.345,-10.73) C17(4.859,-11.071) C18(4.373,-10.73) C19(3.887,-11.071) C20(3.401,-10.73) C21(2.915,-11.071) C22(2.43,-10.73) C23(1.944,-11.071) C24(1.458,-10.73) C25(0.972,-11.071) C26(0.48,-10.715) C27(0,-11.071) C28(-0.48,-10.715) C29(-0.972,-11.071) C30(-1.458,-10.73) C31(-1.944,-11.071) C32(-2.43,-10.73) C33(-2.915,-11.071) C34(-3.401,-10.73) C35(-3.887,-11.071) C36(-4.373,-10.73) C37(-4.859,-11.071) C38(-5.345,-10.73) C39(-5.831,-11.071) C40(-6.317,-10.73) C41(-6.803,-11.071) C42(-7.289,-10.73) C43(-7.774,-11.071) C45(-8.698,-11.028) D27(0,-10.366) H3(11.929,-8.351) H51(-11.929,-8.351) J3(12.071,-7.774) J51(-12.071,-7.774) K2(12.429,-7.289) K3(11.73,-7.289) K51(-11.73,-7.289) K52(-12.429,-7.289) L3(12.071,-6.803) L51(-12.071,-6.803) M2(12.429,-6.317) M3(11.73,-6.317) M51(-11.73,-6.317) M52(-12.429,-6.317) N3(12.071,-5.831) N51(-12.071,-5.831) P2(12.429,-5.345) P3(11.73,-5.345) P51(-11.73,-5.345) P52(-12.429,-5.345) R3(12.071,-4.859) R51(-12.071,-4.859) T2(12.429,-4.373) T3(11.73,-4.373) T51(-11.73,-4.373) T52(-12.429,-4.373) U3(12.071,-3.887) U51(-12.071,-3.887) V2(12.429,-3.401) V3(11.73,-3.401) V51(-11.73,-3.401) V52(-12.429,-3.401) W3(12.071,-2.915) W51(-12.071,-2.915) Y2(12.429,-2.43) Y3(11.73,-2.43) Y51(-11.73,-2.43) Y52(-12.429,-2.43)
  round 0.33 smd: AA16(5.307,-1.961) AA18(4.549,-1.961) AA19(3.791,-1.961) AA21(3.033,-1.961) AA22(2.275,-1.961) AA24(1.516,-1.961) AA25(0.758,-1.961) AA27(0,-1.961) AA29(-0.758,-1.961) AA30(-1.516,-1.961) AA32(-2.275,-1.961) AA33(-3.033,-1.961) AA35(-3.791,-1.961) AA36(-4.549,-1.961) AA38(-5.307,-1.961) AC16(5.307,-1.177) AC18(4.549,-1.177) AC19(3.791,-1.177) AC21(3.033,-1.177) AC22(2.275,-1.177) AC24(1.516,-1.177) AC25(0.758,-1.177) AC27(0,-1.177) AC29(-0.758,-1.177) AC30(-1.516,-1.177) AC32(-2.275,-1.177) AC33(-3.033,-1.177) AC35(-3.791,-1.177) AC36(-4.549,-1.177) AC38(-5.307,-1.177) AD16(5.307,-0.392) AD18(4.549,-0.392) AD19(3.791,-0.392) AD21(3.033,-0.392) AD22(2.275,-0.392) AD24(1.516,-0.392) AD25(0.758,-0.392) AD27(0,-0.392) AD29(-0.758,-0.392) AD30(-1.516,-0.392) AD32(-2.275,-0.392) AD33(-3.033,-0.392) AD35(-3.791,-0.392) AD36(-4.549,-0.392) AD38(-5.307,-0.392) AF16(5.307,0.392) AF18(4.549,0.392) AF19(3.791,0.392) AF21(3.033,0.392) AF22(2.275,0.392) AF24(1.516,0.392) AF25(0.758,0.392) AF27(0,0.392) AF29(-0.758,0.392) AF30(-1.516,0.392) AF32(-2.275,0.392) AF33(-3.033,0.392) AF35(-3.791,0.392) AF36(-4.549,0.392) AF38(-5.307,0.392) AG16(5.307,1.177) AG18(4.549,1.177) AG19(3.791,1.177) AG21(3.033,1.177) AG22(2.275,1.177) AG24(1.516,1.177) AG25(0.758,1.177) AG27(0,1.177) AG29(-0.758,1.177) AG30(-1.516,1.177) AG32(-2.275,1.177) AG33(-3.033,1.177) AG35(-3.791,1.177) AG36(-4.549,1.177) AG38(-5.307,1.177) AJ16(5.307,1.961) AJ18(4.549,1.961) AJ19(3.791,1.961) AJ21(3.033,1.961) AJ22(2.275,1.961) AJ24(1.516,1.961) AJ25(0.758,1.961) AJ27(0,1.961) AJ29(-0.758,1.961) AJ30(-1.516,1.961) AJ32(-2.275,1.961) AJ33(-3.033,1.961) AJ35(-3.791,1.961) AJ36(-4.549,1.961) AJ38(-5.307,1.961) AK16(5.307,2.745) AK18(4.549,2.745) AK19(3.791,2.745) AK21(3.033,2.745) AK22(2.275,2.745) AK24(1.516,2.745) AK25(0.758,2.745) AK27(0,2.745) AK29(-0.758,2.745) AK30(-1.516,2.745) AK32(-2.275,2.745) AK33(-3.033,2.745) AK35(-3.791,2.745) AK36(-4.549,2.745) AK38(-5.307,2.745) AM16(5.307,3.53) AM18(4.549,3.53) AM19(3.791,3.53) AM21(3.033,3.53) AM22(2.275,3.53) AM24(1.516,3.53) AM25(0.758,3.53) AM27(0,3.53) AM29(-0.758,3.53) AM30(-1.516,3.53) AM32(-2.275,3.53) AM33(-3.033,3.53) AM35(-3.791,3.53) AM36(-4.549,3.53) AM38(-5.307,3.53) AN16(5.307,4.314) AN18(4.549,4.314) AN19(3.791,4.314) AN21(3.033,4.314) AN22(2.275,4.314) AN24(1.516,4.314) AN25(0.758,4.314) AN27(0,4.314) AN29(-0.758,4.314) AN30(-1.516,4.314) AN32(-2.275,4.314) AN33(-3.033,4.314) AN35(-3.791,4.314) AN36(-4.549,4.314) AN38(-5.307,4.314) U16(5.307,-4.314) U18(4.549,-4.314) U19(3.791,-4.314) U21(3.033,-4.314) U22(2.275,-4.314) U24(1.516,-4.314) U25(0.758,-4.314) U27(0,-4.314) U29(-0.758,-4.314) U30(-1.516,-4.314) U32(-2.275,-4.314) U33(-3.033,-4.314) U35(-3.791,-4.314) U36(-4.549,-4.314) U38(-5.307,-4.314) V16(5.307,-3.53) V18(4.549,-3.53) V19(3.791,-3.53) V21(3.033,-3.53) V22(2.275,-3.53) V24(1.516,-3.53) V25(0.758,-3.53) V27(0,-3.53) V29(-0.758,-3.53) V30(-1.516,-3.53) V32(-2.275,-3.53) V33(-3.033,-3.53) V35(-3.791,-3.53) V36(-4.549,-3.53) V38(-5.307,-3.53) Y16(5.307,-2.745) Y18(4.549,-2.745) Y19(3.791,-2.745) Y21(3.033,-2.745) Y22(2.275,-2.745) Y24(1.516,-2.745) Y25(0.758,-2.745) Y27(0,-2.745) Y29(-0.758,-2.745) Y30(-1.516,-2.745) Y32(-2.275,-2.745) Y33(-3.033,-2.745) Y35(-3.791,-2.745) Y36(-4.549,-2.745) Y38(-5.307,-2.745)
  round 0.305 smd: AB4(11.137,-1.448) AB6(10.463,-1.448) AB7(9.752,-1.448) AB9(9.041,-1.448) AB10(8.33,-1.448) AB12(7.618,-1.448) AB13(6.907,-1.448) AB14(6.196,-1.448) AB40(-6.196,-1.448) AB41(-6.907,-1.448) AB42(-7.618,-1.448) AB44(-8.33,-1.448) AB45(-9.041,-1.448) AB47(-9.752,-1.448) AB48(-10.463,-1.448) AB50(-11.137,-1.448) AD4(10.995,-0.463) AD6(10.404,-0.525) AD7(9.752,-0.475) AD9(9.041,-0.475) AD10(8.33,-0.475) AD12(7.618,-0.475) AD13(6.907,-0.475) AD14(6.196,-0.475) AD40(-6.196,-0.475) AD41(-6.907,-0.475) AD42(-7.618,-0.475) AD44(-8.33,-0.475) AD45(-9.041,-0.475) AD47(-9.752,-0.475) AD48(-10.404,-0.525) AD50(-10.995,-0.463) AE6(10.108,0) AE8(9.396,0) AE9(8.685,0) AE11(7.974,0) AE12(7.263,0) AE14(6.552,0) AE40(-6.552,0) AE42(-7.263,0) AE43(-7.974,0) AE45(-8.685,0) AE46(-9.396,0) AE48(-10.108,0) AF4(10.995,0.463) AF6(10.404,0.525) AF7(9.752,0.475) AF9(9.041,0.475) AF10(8.33,0.475) AF12(7.618,0.475) AF13(6.907,0.475) AF14(6.196,0.475) AF40(-6.196,0.475) AF41(-6.907,0.475) AF42(-7.618,0.475) AF44(-8.33,0.475) AF45(-9.041,0.475) AF47(-9.752,0.475) AF48(-10.404,0.525) AF50(-10.995,0.463) AH4(11.137,1.448) AH6(10.463,1.448) AH7(9.752,1.448) AH9(9.041,1.448) AH10(8.33,1.448) AH12(7.618,1.448) AH13(6.907,1.448) AH14(6.196,1.448) AH40(-6.196,1.448) AH41(-6.907,1.448) AH42(-7.618,1.448) AH44(-8.33,1.448) AH45(-9.041,1.448) AH47(-9.752,1.448) AH48(-10.463,1.448) AH50(-11.137,1.448) AK4(11.137,2.439) AK6(10.463,2.439) AK7(9.752,2.439) AK9(9.041,2.439) AK10(8.33,2.439) AK12(7.618,2.439) AK13(6.907,2.439) AK14(6.196,2.439) AK40(-6.196,2.439) AK41(-6.907,2.439) AK42(-7.618,2.439) AK44(-8.33,2.439) AK45(-9.041,2.439) AK47(-9.752,2.439) AK48(-10.463,2.439) AK50(-11.137,2.439) AM4(11.137,3.386) AM6(10.463,3.412) AM7(9.752,3.412) AM9(9.041,3.412) AM10(8.33,3.412) AM12(7.618,3.412) AM13(6.907,3.412) AM14(6.196,3.412) AM40(-6.196,3.412) AM41(-6.907,3.412) AM42(-7.618,3.412) AM44(-8.33,3.412) AM45(-9.041,3.412) AM47(-9.752,3.412) AM48(-10.463,3.412) AM50(-11.137,3.386) AN5(10.819,3.887) AN6(10.108,3.887) AN8(9.396,3.887) AN9(8.685,3.887) AN11(7.974,3.887) AN12(7.263,3.887) AN14(6.552,3.887) AN40(-6.552,3.887) AN42(-7.263,3.887) AN43(-7.974,3.887) AN45(-8.685,3.887) AN46(-9.396,3.887) AN48(-10.108,3.887) AN49(-10.819,3.887) AP4(11.137,4.388) AP6(10.463,4.362) AP7(9.752,4.362) AP9(9.041,4.362) AP10(8.33,4.362) AP12(7.618,4.362) AP13(6.907,4.362) AP14(6.196,4.362) AP40(-6.196,4.362) AP41(-6.907,4.362) AP42(-7.618,4.362) AP44(-8.33,4.362) AP45(-9.041,4.362) AP47(-9.752,4.362) AP48(-10.463,4.362) AP50(-11.137,4.388) AT4(11.137,5.336) AT6(10.463,5.336) AT7(9.752,5.336) AT9(9.041,5.336) AT10(8.33,5.336) AT12(7.618,5.336) AT13(6.907,5.336) AT14(6.305,5.336) AT16(5.336,5.196) AT18(4.362,5.196) AT19(3.887,5.552) AT20(3.412,5.196) AT22(2.439,5.196) AT24(1.448,5.196) AT26(0.475,5.196) AT27(0,5.552) AT28(-0.475,5.196) AT30(-1.448,5.196) AT32(-2.439,5.196) AT34(-3.412,5.196) AT35(-3.887,5.552) AT36(-4.362,5.196) AT38(-5.336,5.196) AT40(-6.305,5.336) AT41(-6.907,5.336) AT42(-7.618,5.336) AT44(-8.33,5.336) AT45(-9.041,5.336) AT47(-9.752,5.336) AT48(-10.463,5.336) AT50(-11.137,5.336) AU16(5.336,5.907) AU18(4.362,5.907) AU20(3.412,5.907) AU22(2.439,5.907) AU24(1.448,5.907) AU26(0.475,5.907) AU28(-0.475,5.907) AU30(-1.448,5.907) AU32(-2.439,5.907) AU34(-3.412,5.907) AU36(-4.362,5.907) AU38(-5.336,5.907) AV4(11.137,6.326) AV6(10.463,6.326) AV7(9.752,6.326) AV9(9.041,6.326) AV10(8.33,6.326) AV12(7.618,6.326) AV13(6.907,6.326) AV14(6.326,6.446) AV16(5.336,6.618) AV18(4.362,6.618) AV19(3.887,6.263) AV20(3.412,6.618) AV22(2.439,6.618) AV24(1.448,6.618) AV26(0.475,6.618) AV27(0,6.263) AV28(-0.475,6.618) AV30(-1.448,6.618) AV32(-2.439,6.618) AV34(-3.412,6.618) AV35(-3.887,6.263) AV36(-4.362,6.618) AV38(-5.336,6.618) AV40(-6.326,6.446) AV41(-6.907,6.326) AV42(-7.618,6.326) AV44(-8.33,6.326) AV45(-9.041,6.326) AV47(-9.752,6.326) AV48(-10.463,6.326) AV50(-11.137,6.326) AW13(6.751,6.915) AW19(3.887,6.974) AW27(0,6.974) AW35(-3.887,6.974) AW41(-6.751,6.915) AY4(11.137,7.317) AY6(10.463,7.317) AY7(9.752,7.317) AY9(9.041,7.317) AY10(8.33,7.317) AY12(7.317,7.34) AY14(6.326,7.33) AY16(5.336,7.33) AY18(4.362,7.33) AY20(3.412,7.33) AY22(2.439,7.33) AY24(1.448,7.33) AY26(0.475,7.33) AY28(-0.475,7.33) AY30(-1.448,7.33) AY32(-2.439,7.33) AY34(-3.412,7.33) AY36(-4.362,7.33) AY38(-5.336,7.33) AY40(-6.326,7.33) AY42(-7.317,7.34) AY44(-8.33,7.317) AY45(-9.041,7.317) AY47(-9.752,7.317) AY48(-10.463,7.317) AY50(-11.137,7.317) B7(9.852,-11.23) B47(-9.852,-11.23) BA12(7.317,8.041) BA14(6.326,8.041) BA16(5.336,8.041) BA18(4.362,8.041) BA19(3.887,7.685) BA20(3.412,8.041) BA22(2.439,8.041) BA24(1.448,8.041) BA26(0.475,8.041) BA27(0,7.685) BA28(-0.475,8.041) BA30(-1.448,8.041) BA32(-2.439,8.041) BA34(-3.412,8.041) BA35(-3.887,7.685) BA36(-4.362,8.041) BA38(-5.336,8.041) BA40(-6.326,8.041) BA42(-7.317,8.041) BB4(11.258,8.307) BB5(10.547,8.307) BB7(9.835,8.307) BB8(9.124,8.307) BB10(8.307,8.17) BB19(3.887,8.396) BB27(0,8.396) BB35(-3.887,8.396) BB44(-8.307,8.17) BB46(-9.124,8.307) BB47(-9.835,8.307) BB49(-10.547,8.307) BB50(-11.258,8.307) BC10(8.307,8.764) BC12(7.317,8.752) BC14(6.326,8.752) BC16(5.336,8.752) BC18(4.362,8.752) BC20(3.412,8.752) BC22(2.439,8.752) BC24(1.448,8.752) BC26(0.475,8.752) BC28(-0.475,8.752) BC30(-1.448,8.752) BC32(-2.439,8.752) BC34(-3.412,8.752) BC36(-4.362,8.752) BC38(-5.336,8.752) BC40(-6.326,8.752) BC42(-7.317,8.752) BC44(-8.307,8.764) BD5(10.565,9.302) BD7(9.712,9.302) BD10(8.307,9.457) BD12(7.317,9.463) BD14(6.326,9.463) BD16(5.336,9.463) BD18(4.362,9.463) BD19(3.887,9.108) BD20(3.412,9.463) BD22(2.439,9.463) BD24(1.448,9.463) BD26(0.525,9.404) BD27(0,9.108) BD28(-0.525,9.404) BD30(-1.448,9.463) BD32(-2.439,9.463) BD34(-3.412,9.463) BD35(-3.887,9.108) BD36(-4.362,9.463) BD38(-5.336,9.463) BD40(-6.326,9.463) BD42(-7.317,9.463) BD44(-8.307,9.457) BD47(-9.712,9.302) BD49(-10.565,9.302) BE3(11.643,9.58) BE8(9.32,9.747) BE19(3.887,9.819) BE35(-3.887,9.819) BE46(-9.32,9.747) BE51(-11.643,9.58) BF4(11.163,10.163) BF6(10.113,10.238) BF10(8.307,10.168) BF12(7.317,10.137) BF14(6.326,10.137) BF16(5.336,10.137) BF18(4.388,10.137) BF20(3.386,10.137) BF22(2.439,10.137) BF24(1.448,10.137) BF26(0.463,9.995) BF28(-0.463,9.995) BF30(-1.448,10.137) BF32(-2.439,10.137) BF34(-3.386,10.137) BF36(-4.388,10.137) BF38(-5.336,10.137) BF40(-6.326,10.137) BF42(-7.317,10.137) BF44(-8.307,10.168) BF48(-10.113,10.238) BF50(-11.163,10.163) BG5(10.58,10.643) BG7(9.553,10.709) BG47(-9.553,10.709) BG49(-10.58,10.643) BH7(9.852,11.23) BH47(-9.852,11.23) C5(10.58,-10.643) C7(9.553,-10.709) C47(-9.553,-10.709) C49(-10.58,-10.643) D4(11.163,-10.163) D6(10.113,-10.238) D10(8.307,-10.168) D12(7.317,-10.137) D14(6.326,-10.137) D16(5.336,-10.137) D18(4.388,-10.137) D20(3.386,-10.137) D22(2.439,-10.137) D24(1.448,-10.137) D26(0.463,-9.995) D28(-0.463,-9.995) D30(-1.448,-10.137) D32(-2.439,-10.137) D34(-3.386,-10.137) D36(-4.388,-10.137) D38(-5.336,-10.137) D40(-6.326,-10.137) D42(-7.317,-10.137) D44(-8.307,-10.168) D48(-10.113,-10.238) D50(-11.163,-10.163) E3(11.643,-9.58) E8(9.32,-9.747) E19(3.887,-9.819) E35(-3.887,-9.819) E46(-9.32,-9.747) E51(-11.643,-9.58) F5(10.565,-9.302) F7(9.712,-9.302) F10(8.307,-9.457) F12(7.317,-9.463) F14(6.326,-9.463) F16(5.336,-9.463) F18(4.362,-9.463) F19(3.887,-9.108) F20(3.412,-9.463) F22(2.439,-9.463) F24(1.448,-9.463) F26(0.525,-9.404) F27(0,-9.108) F28(-0.525,-9.404) F30(-1.448,-9.463) F32(-2.439,-9.463) F34(-3.412,-9.463) F35(-3.887,-9.108) F36(-4.362,-9.463) F38(-5.336,-9.463) F40(-6.326,-9.463) F42(-7.317,-9.463) F44(-8.307,-9.457) F47(-9.712,-9.302) F49(-10.565,-9.302) G10(8.307,-8.764) G12(7.317,-8.752) G14(6.326,-8.752) G16(5.336,-8.752) G18(4.362,-8.752) G20(3.412,-8.752) G22(2.439,-8.752) G24(1.448,-8.752) G26(0.475,-8.752) G28(-0.475,-8.752) G30(-1.448,-8.752) G32(-2.439,-8.752) G34(-3.412,-8.752) G36(-4.362,-8.752) G38(-5.336,-8.752) G40(-6.326,-8.752) G42(-7.317,-8.752) G44(-8.307,-8.764) H4(11.258,-8.307) H5(10.547,-8.307) H7(9.835,-8.307) H8(9.124,-8.307) H10(8.307,-8.17) H19(3.887,-8.396) H27(0,-8.396) H35(-3.887,-8.396) H44(-8.307,-8.17) H46(-9.124,-8.307) H47(-9.835,-8.307) H49(-10.547,-8.307) H50(-11.258,-8.307) J12(7.317,-8.041) J14(6.326,-8.041) J16(5.336,-8.041) J18(4.362,-8.041) J19(3.887,-7.685) J20(3.412,-8.041) J22(2.439,-8.041) J24(1.448,-8.041) J26(0.475,-8.041) J27(0,-7.685) J28(-0.475,-8.041) J30(-1.448,-8.041) J32(-2.439,-8.041) J34(-3.412,-8.041) J35(-3.887,-7.685) J36(-4.362,-8.041) J38(-5.336,-8.041) J40(-6.326,-8.041) J42(-7.317,-8.041) K4(11.137,-7.317) K6(10.463,-7.317) K7(9.752,-7.317) K9(9.041,-7.317) K10(8.33,-7.317) K12(7.317,-7.34) K14(6.326,-7.33) K16(5.336,-7.33) K18(4.362,-7.33) K20(3.412,-7.33) K22(2.439,-7.33) K24(1.448,-7.33) K26(0.475,-7.33) K28(-0.475,-7.33) K30(-1.448,-7.33) K32(-2.439,-7.33) K34(-3.412,-7.33) K36(-4.362,-7.33) K38(-5.336,-7.33) K40(-6.326,-7.33) K42(-7.317,-7.34) K44(-8.33,-7.317) K45(-9.041,-7.317) K47(-9.752,-7.317) K48(-10.463,-7.317) K50(-11.137,-7.317) L13(6.751,-6.915) L19(3.887,-6.974) L27(0,-6.974) L35(-3.887,-6.974) L41(-6.751,-6.915) M4(11.137,-6.326) M6(10.463,-6.326) M7(9.752,-6.326) M9(9.041,-6.326) M10(8.33,-6.326) M12(7.618,-6.326) M13(6.907,-6.326) M14(6.326,-6.446) M16(5.336,-6.618) M18(4.362,-6.618) M19(3.887,-6.263) M20(3.412,-6.618) M22(2.439,-6.618) M24(1.448,-6.618) M26(0.475,-6.618) M27(0,-6.263) M28(-0.475,-6.618) M30(-1.448,-6.618) M32(-2.439,-6.618) M34(-3.412,-6.618) M35(-3.887,-6.263) M36(-4.362,-6.618) M38(-5.336,-6.618) M40(-6.326,-6.446) M41(-6.907,-6.326) M42(-7.618,-6.326) M44(-8.33,-6.326) M45(-9.041,-6.326) M47(-9.752,-6.326) M48(-10.463,-6.326) M50(-11.137,-6.326) N16(5.336,-5.907) N18(4.362,-5.907) N20(3.412,-5.907) N22(2.439,-5.907) N24(1.448,-5.907) N26(0.475,-5.907) N28(-0.475,-5.907) N30(-1.448,-5.907) N32(-2.439,-5.907) N34(-3.412,-5.907) N36(-4.362,-5.907) N38(-5.336,-5.907) P4(11.137,-5.336) P6(10.463,-5.336) P7(9.752,-5.336) P9(9.041,-5.336) P10(8.33,-5.336) P12(7.618,-5.336) P13(6.907,-5.336) P14(6.305,-5.336) P16(5.336,-5.196) P18(4.362,-5.196) P19(3.887,-5.552) P20(3.412,-5.196) P22(2.439,-5.196) P24(1.448,-5.196) P26(0.475,-5.196) P27(0,-5.552) P28(-0.475,-5.196) P30(-1.448,-5.196) P32(-2.439,-5.196) P34(-3.412,-5.196) P35(-3.887,-5.552) P36(-4.362,-5.196) P38(-5.336,-5.196) P40(-6.305,-5.336) P41(-6.907,-5.336) P42(-7.618,-5.336) P44(-8.33,-5.336) P45(-9.041,-5.336) P47(-9.752,-5.336) P48(-10.463,-5.336) P50(-11.137,-5.336) T4(11.137,-4.388) T6(10.463,-4.362) T7(9.752,-4.362) T9(9.041,-4.362) T10(8.33,-4.362) T12(7.618,-4.362) T13(6.907,-4.362) T14(6.196,-4.362) T40(-6.196,-4.362) T41(-6.907,-4.362) T42(-7.618,-4.362) T44(-8.33,-4.362) T45(-9.041,-4.362) T47(-9.752,-4.362) T48(-10.463,-4.362) T50(-11.137,-4.388) U5(10.819,-3.887) U6(10.108,-3.887) U8(9.396,-3.887) U9(8.685,-3.887) U11(7.974,-3.887) U12(7.263,-3.887) U14(6.552,-3.887) U40(-6.552,-3.887) U42(-7.263,-3.887) U43(-7.974,-3.887) U45(-8.685,-3.887) U46(-9.396,-3.887) U48(-10.108,-3.887) U49(-10.819,-3.887) V4(11.137,-3.386) V6(10.463,-3.412) V7(9.752,-3.412) V9(9.041,-3.412) V10(8.33,-3.412) V12(7.618,-3.412) V13(6.907,-3.412) V14(6.196,-3.412) V40(-6.196,-3.412) V41(-6.907,-3.412) V42(-7.618,-3.412) V44(-8.33,-3.412) V45(-9.041,-3.412) V47(-9.752,-3.412) V48(-10.463,-3.412) V50(-11.137,-3.386) Y4(11.137,-2.439) Y6(10.463,-2.439) Y7(9.752,-2.439) Y9(9.041,-2.439) Y10(8.33,-2.439) Y12(7.618,-2.439) Y13(6.907,-2.439) Y14(6.196,-2.439) Y40(-6.196,-2.439) Y41(-6.907,-2.439) Y42(-7.618,-2.439) Y44(-8.33,-2.439) Y45(-9.041,-2.439) Y47(-9.752,-2.439) Y48(-10.463,-2.439) Y50(-11.137,-2.439)
CAE630W570HN
  rect 3.5x1.6 smd: 1(-2.85,0) 2(2.85,0)
CAE660W800HN
  rect 3.35x1.6 smd: 1(-2.45,0) 2(2.45,0)
CC0402N
  rect 0.55x0.5 smd: 1(-0.475,0) 2(0.475,0)
CC0603N
  rect 0.8x0.8 smd: 1(-0.75,0) 2(0.75,0)
CC0805N
  rect 1x1.2 smd: 1(-1,0) 2(1,0)
CC1206N
  rect 1.2x1.6 smd: 1(-1.6,0) 2(1.6,0)
CC1210N
  rect 1.3x2.6 smd: 1(-1.4,0) 2(1.4,0)
CC5750N
  rect 1.4x5 smd: 1(-2.75,0) 2(2.75,0)
CCP7343N
  rect 2.6x2.6 smd: 1(-3.05,0) 2(3.05,0)
F1206N
  rect 1.3x1.8 smd: 1(-1.45,0) 2(1.45,0)
FB0603N
  rect 0.8x0.8 smd: 1(-0.75,0) 2(0.75,0)
FB0805N
  rect 1x1.2 smd: 1(-1,0) 2(1,0)
FIL_175P200X120-4L
  rect 0.6x0.7 smd: 1(-0.5,0.875) 2(-0.5,-0.875) 3(0.5,-0.875) 4(0.5,0.875)
KPAK127P605-9N
  rect 0.9x1.5 smd: (-1.757,1.811)
  rect 0.7x0.5 smd: 1(-2.79,1.905) 3(2.79,-1.905) 4(2.79,-0.635) 5(2.79,0.635) 6(2.79,1.905)
  rect 1.85x3 smd: 2(-2.215,-0.637)
  rect 2.6x4.8 smd: 7(0.47,0.004)
LC3030DL
  rect 1.5x3.2 smd: 1(-1.05,0) 2(1.05,0)
LC3225BN
  rect 1x2.7 smd: 1(-1.3,0) 2(1.3,0)
LC6666N
  rect 2.3x3.3 smd: 1(-3.075,0) 2(3.075,0)
LC7266N
  rect 3.5x2.6 smd: 1(0,3.15) 2(0,-3.15)
LED1706N
  rect 0.8x0.8 smd: 1(0.85,0) 2(-0.85,0)
LEDC0603N
  rect 0.81x0.81 smd: 1(0,0.75) 2(0,-0.75)
LQFP40P1600X1600-128N
  oval 1.3x0.2 smd: 1(-7.65,6.2) 2(-7.65,5.8) 3(-7.65,5.4) 4(-7.65,5) 5(-7.65,4.6) 6(-7.65,4.2) 7(-7.65,3.8) 8(-7.65,3.4) 9(-7.65,3) 10(-7.65,2.6) 11(-7.65,2.2) 12(-7.65,1.8) 13(-7.65,1.4) 14(-7.65,1) 15(-7.65,0.6) 16(-7.65,0.2) 17(-7.65,-0.2) 18(-7.65,-0.6) 19(-7.65,-1) 20(-7.65,-1.4) 21(-7.65,-1.8) 22(-7.65,-2.2) 23(-7.65,-2.6) 24(-7.65,-3) 25(-7.65,-3.4) 26(-7.65,-3.8) 27(-7.65,-4.2) 28(-7.65,-4.6) 29(-7.65,-5) 30(-7.65,-5.4) 31(-7.65,-5.8) 32(-7.65,-6.2) 65(7.65,-6.2) 66(7.65,-5.8) 67(7.65,-5.4) 68(7.65,-5) 69(7.65,-4.6) 70(7.65,-4.2) 71(7.65,-3.8) 72(7.65,-3.4) 73(7.65,-3) 74(7.65,-2.6) 75(7.65,-2.2) 76(7.65,-1.8) 77(7.65,-1.4) 78(7.65,-1) 79(7.65,-0.6) 80(7.65,-0.2) 81(7.65,0.2) 82(7.65,0.6) 83(7.65,1) 84(7.65,1.4) 85(7.65,1.8) 86(7.65,2.2) 87(7.65,2.6) 88(7.65,3) 89(7.65,3.4) 90(7.65,3.8) 91(7.65,4.2) 92(7.65,4.6) 93(7.65,5) 94(7.65,5.4) 95(7.65,5.8) 96(7.65,6.2)
  oval 0.2x1.3 smd: 33(-6.2,-7.65) 34(-5.8,-7.65) 35(-5.4,-7.65) 36(-5,-7.65) 37(-4.6,-7.65) 38(-4.2,-7.65) 39(-3.8,-7.65) 40(-3.4,-7.65) 41(-3,-7.65) 42(-2.6,-7.65) 43(-2.2,-7.65) 44(-1.8,-7.65) 45(-1.4,-7.65) 46(-1,-7.65) 47(-0.6,-7.65) 48(-0.2,-7.65) 49(0.2,-7.65) 50(0.6,-7.65) 51(1,-7.65) 52(1.4,-7.65) 53(1.8,-7.65) 54(2.2,-7.65) 55(2.6,-7.65) 56(3,-7.65) 57(3.4,-7.65) 58(3.8,-7.65) 59(4.2,-7.65) 60(4.6,-7.65) 61(5,-7.65) 62(5.4,-7.65) 63(5.8,-7.65) 64(6.2,-7.65) 97(6.2,7.65) 98(5.8,7.65) 99(5.4,7.65) 100(5,7.65) 101(4.6,7.65) 102(4.2,7.65) 103(3.8,7.65) 104(3.4,7.65) 105(3,7.65) 106(2.6,7.65) 107(2.2,7.65) 108(1.8,7.65) 109(1.4,7.65) 110(1,7.65) 111(0.6,7.65) 112(0.2,7.65) 113(-0.2,7.65) 114(-0.6,7.65) 115(-1,7.65) 116(-1.4,7.65) 117(-1.8,7.65) 118(-2.2,7.65) 119(-2.6,7.65) 120(-3,7.65) 121(-3.4,7.65) 122(-3.8,7.65) 123(-4.2,7.65) 124(-4.6,7.65) 125(-5,7.65) 126(-5.4,7.65) 127(-5.8,7.65) 128(-6.2,7.65)
MARK-D100D250
  round 1 smd: 1(0,0)
MIC_FOM6050MP3_190P
  round 1.3 hole 0.8: 1(-0.95,0) 2(0.95,0)
MTG230H600
  round 6 hole 2.3: 1(0,0)
MTG250H500
  round 5 hole 2.5: 1(0,0)
MTG340H580_TOP
  round 5.8 hole 3.4: 1(0,0)
MTG340H600
  round 6 hole 3.4: 1(0,0)
OSC120P150X670-4L
  rect 0.6x0.9 smd: 1(-0.6,3.3) 2(-0.6,-3.3) 3(0.6,-3.3) 4(0.6,3.3)
OSC127P200X600-2L
  rect 0.6x2.5 smd: 1(-0.6,4.98) 2(0.6,4.98)
OSC170P320X250-4N
  rect 1.4x1.15 smd: 1(-1.1,-0.85) 2(1.1,-0.85) 3(1.1,0.85) 4(-1.1,0.85)
QFN40P300X300-20N
  oval 0.6x0.2 smd: 1(-1.4,0.8) 2(-1.4,0.4) 3(-1.4,0) 4(-1.4,-0.4) 5(-1.4,-0.8) 11(1.4,-0.8) 12(1.4,-0.4) 13(1.4,0) 14(1.4,0.4) 15(1.4,0.8)
  oval 0.2x0.6 smd: 6(-0.8,-1.4) 7(-0.4,-1.4) 8(0,-1.4) 9(0.4,-1.4) 10(0.8,-1.4) 16(0.8,1.4) 17(0.4,1.4) 18(0,1.4) 19(-0.4,1.4) 20(-0.8,1.4)
  rect 1.8x1.8 smd: E1(0,0)
